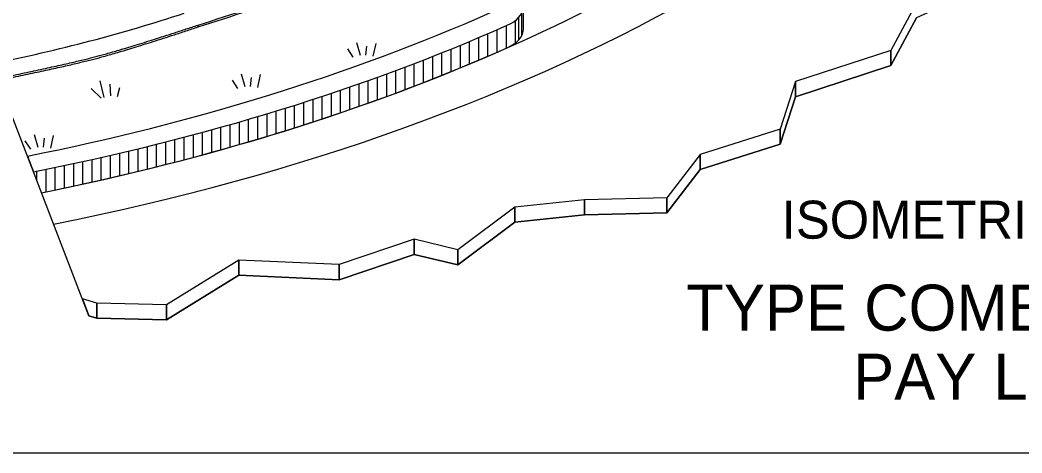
# Model space of a CAD drawing. Extents: x 103862 to 107151, y 100000 to 102076.
# Drawn here: x 105680.3 to 106115.6, y 99999.5 to 100187.5 of the extents above; entities that cross this region are included whole.
import ezdxf

# ---------------------------------------------------------------- set-up
doc = ezdxf.new("R2010")
doc.units = 0
for name, color, linetype in [('Level 1', 7, 'Continuous'), ('Level 10', 7, 'Continuous'), ('Level 11', 7, 'Continuous'), ('Level 18', 7, 'Continuous'), ('Level 19', 7, 'Continuous'), ('Level 2', 7, 'Continuous'), ('Level 20', 7, 'Continuous'), ('Level 3', 7, 'Continuous'), ('Level 4', 7, 'Continuous'), ('Level 45', 7, 'Continuous'), ('Level 57', 7, 'Continuous')]:
    doc.layers.add(name, color=color, linetype=linetype)

msp = doc.modelspace()

# ---------------------------------------------------------------- linework, layer by layer
at = {"layer": 'Level 1'}
msp.add_lwpolyline([(103862, 99999.5), (107151, 99999.5), (107151, 102075.5), (103862, 102075.5)], close=True, dxfattribs=at)
msp.add_lwpolyline([(103862, 99999.5), (107151, 99999.5), (107151, 102075.5), (103862, 102075.5)], close=True, dxfattribs=at)
msp.add_lwpolyline([(103862, 99999.5), (107151, 99999.5), (107151, 102075.5), (103862, 102075.5)], close=True, dxfattribs=at)
at = {"layer": 'Level 10'}
msp.add_line((105757.65, 100184.51), (105757.65, 100185.33), dxfattribs=at)
at = {"layer": 'Level 11'}
msp.add_line((105710.23, 100059.06), (105641.33, 100237.57), dxfattribs=at)
msp.add_lwpolyline([(106115.72, 100230.53), (106112.39, 100207.89), (106069.84, 100188.51), (106058.66, 100167.81), (106017.22, 100154.24), (106010.53, 100133.55), (105975.81, 100122.57), (105961.27, 100103.81), (105925.56, 100102.93), (105895.31, 100099.71), (105870.54, 100081.21), (105851.49, 100085.75), (105819.01, 100074.76), (105775.31, 100076.72), (105743.96, 100057.33), (105713.71, 100057.99), (105710.23, 100059.06)], dxfattribs=at)
at = {"layer": 'Level 18'}
for p, q in [((105826.49, 100177.77), (105828.07, 100172.23)), ((105822.53, 100175), (105824.9, 100171.44)), ((105830.84, 100176.19), (105830.44, 100172.23)), ((105834.8, 100177.38), (105833.61, 100171.83)), ((105716.88, 100153.95), (105715.1, 100161.06)), ((105772.38, 100161.43), (105774.75, 100157.86)), ((105776.33, 100164.2), (105777.92, 100158.66)), ((105780.69, 100162.62), (105780.29, 100158.66)), ((105784.64, 100163.8), (105783.46, 100158.26)), ((105715.46, 100153.59), (105711.19, 100157.86)), ((105719.72, 100154.66), (105719.36, 100159.64)), ((105722.56, 100154.3), (105723.63, 100158.21)), ((105682.42, 100135.02), (105684.79, 100131.45)), ((105686.37, 100137.79), (105687.96, 100132.25)), ((105690.73, 100136.21), (105690.33, 100132.25)), ((105694.68, 100137.39), (105693.5, 100131.85))]:
    msp.add_line(p, q, dxfattribs=at)
at = {"layer": 'Level 19'}
for p, q in [((105898.32, 100180.79), (105898.32, 100190.6)), ((105895.59, 100177.62), (105895.59, 100187.43)), ((105897.04, 100178.95), (105897.04, 100188.76)), ((105887.59, 100173.56), (105887.59, 100183.36)), ((105891.59, 100175.3), (105891.59, 100185.1)), ((105875.59, 100168.45), (105875.59, 100178.25)), ((105879.59, 100170.1), (105879.59, 100179.9)), ((105883.59, 100171.83), (105883.59, 100181.63)), ((105863.59, 100163.54), (105863.59, 100173.34)), ((105867.59, 100165.14), (105867.59, 100174.93)), ((105871.59, 100166.79), (105871.59, 100176.59)), ((105855.59, 100160.38), (105855.59, 100170.17)), ((105859.59, 100161.96), (105859.59, 100171.76)), ((105843.59, 100155.82), (105843.59, 100165.62)), ((105847.59, 100157.34), (105847.59, 100167.13)), ((105851.59, 100158.85), (105851.59, 100168.65)), ((105831.59, 100151.46), (105831.59, 100161.26)), ((105835.59, 100152.91), (105835.59, 100162.7)), ((105839.59, 100154.35), (105839.59, 100164.15)), ((105815.59, 100145.92), (105815.59, 100155.72)), ((105819.59, 100147.29), (105819.59, 100157.09)), ((105823.59, 100148.67), (105823.59, 100158.47)), ((105827.59, 100150.04), (105827.59, 100159.84)), ((105803.59, 100141.98), (105803.59, 100151.78)), ((105807.59, 100143.3), (105807.59, 100153.09)), ((105811.59, 100144.61), (105811.59, 100154.41)), ((105791.59, 100138.23), (105791.59, 100148.02)), ((105795.59, 100139.48), (105795.59, 100149.27)), ((105799.59, 100140.72), (105799.59, 100150.52)), ((105775.59, 100133.46), (105775.59, 100143.26)), ((105779.59, 100134.64), (105779.59, 100144.43)), ((105783.59, 100135.82), (105783.59, 100145.62)), ((105787.59, 100137.01), (105787.59, 100146.81)), ((105759.59, 100129), (105759.59, 100138.8)), ((105763.59, 100130.08), (105763.59, 100139.88)), ((105767.59, 100131.21), (105767.59, 100141)), ((105771.59, 100132.33), (105771.59, 100142.13)), ((105743.59, 100124.81), (105743.59, 100134.61)), ((105747.59, 100125.81), (105747.59, 100135.61)), ((105751.59, 100126.87), (105751.59, 100136.66)), ((105755.59, 100127.93), (105755.59, 100137.73)), ((105723.59, 100119.93), (105723.59, 100129.73)), ((105727.59, 100120.88), (105727.59, 100130.68)), ((105731.59, 100121.83), (105731.59, 100131.63)), ((105735.59, 100122.79), (105735.59, 100132.59)), ((105739.59, 100123.8), (105739.59, 100133.6)), ((105703.59, 100115.46), (105703.59, 100125.26)), ((105707.59, 100116.32), (105707.59, 100126.11)), ((105711.59, 100117.21), (105711.59, 100127.01)), ((105715.59, 100118.1), (105715.59, 100127.9)), ((105719.59, 100118.99), (105719.59, 100128.8)), ((105687.59, 100117.7), (105687.59, 100121.97)), ((105691.59, 100112.96), (105691.59, 100122.76)), ((105695.59, 100113.79), (105695.59, 100123.58)), ((105699.59, 100114.62), (105699.59, 100124.42))]:
    msp.add_line(p, q, dxfattribs=at)
at = {"layer": 'Level 2'}
msp.add_line((105899.05, 100183.72), (105899.05, 100193.52), dxfattribs=at)
msp.add_lwpolyline([(105683.44, 100128.45), (105686.07, 100121.65)], dxfattribs=at)
for centre, major_axis, ratio, start_param, end_param in [((105306.07, 100601.97), (893.91, 0), 0.54007, 5.241973, 5.356974), ((105306.07, 100601.15), (893.91, 0), 0.54007, 5.241973, 5.356974), ((105881.05, 100193.52), (18, 0), 0.57735, 5.36666, 7.068584), ((105500.85, 100431.43), (496.32, 0), 0.562493, 5.055802, 5.241972), ((105453.82, 100515.12), (708, 0), 0.57735, 5.042683, 5.36666), ((105453.82, 100515.12), (720, 0), 0.57735, 5.040825, 5.36666), ((105453.82, 100505.32), (720, 0), 0.57735, 5.045984, 5.36666)]:
    msp.add_ellipse(centre, major_axis=major_axis, ratio=ratio, start_param=start_param, end_param=end_param, dxfattribs=at)
for points in [[(105670.47, 100162.16), (105699.91, 100168.14), (105727.47, 100175.4), (105757.65, 100185.33)], [(105670.69, 100161.35), (105699.26, 100167.14), (105727.18, 100174.49), (105757.65, 100184.51)]]:
    msp.add_open_spline(points, degree=2, dxfattribs=at)
at = {"layer": 'Level 3'}
msp.add_lwpolyline([(105757.65, 100185.33), (105757.65, 100185.33)], dxfattribs=at)
at = {"layer": 'Level 4'}
for centre, major_axis, start_param, end_param in [((105453.82, 100505.32), (720, 0), 5.045984, 5.632303), ((105453.82, 100505.32), (744, 0), 5.04228, 5.497787), ((105881.05, 100183.72), (18, 0), 5.36666, 6.283699)]:
    msp.add_ellipse(centre, major_axis=major_axis, ratio=0.57735, start_param=start_param, end_param=end_param, dxfattribs=at)
at = {"layer": 'Level 45'}
for p, q in [((106069.84, 100195.04), (106058.66, 100174.34)), ((106058.66, 100167.81), (106069.84, 100188.51)), ((106058.66, 100174.34), (106017.22, 100160.78)), ((106058.66, 100174.34), (106058.66, 100167.81)), ((106058.66, 100167.81), (106058.66, 100174.34)), ((106017.22, 100154.24), (106058.66, 100167.81)), ((106017.22, 100160.78), (106010.53, 100140.08)), ((106017.22, 100160.78), (106017.22, 100154.24)), ((106017.22, 100154.24), (106017.22, 100160.78)), ((106010.53, 100133.55), (106017.22, 100154.24)), ((106010.53, 100140.08), (105975.81, 100129.1)), ((106010.53, 100140.08), (106010.53, 100133.55)), ((106010.53, 100133.55), (106010.53, 100140.08)), ((105975.81, 100122.57), (106010.53, 100133.55)), ((105975.81, 100129.1), (105961.27, 100110.34)), ((105975.81, 100129.1), (105975.81, 100122.57)), ((105975.81, 100122.57), (105975.81, 100129.1)), ((105961.27, 100103.81), (105975.81, 100122.57)), ((105925.56, 100109.46), (105895.31, 100106.24)), ((105961.27, 100110.34), (105925.56, 100109.46)), ((105925.56, 100109.46), (105925.56, 100102.93)), ((105925.56, 100102.93), (105925.56, 100109.46)), ((105961.27, 100110.34), (105961.27, 100103.81)), ((105961.27, 100103.81), (105961.27, 100110.34)), ((105895.31, 100106.24), (105870.54, 100087.74)), ((105895.31, 100106.24), (105895.31, 100099.71)), ((105895.31, 100099.71), (105895.31, 100106.24)), ((105925.56, 100102.93), (105961.27, 100103.81)), ((105870.54, 100081.21), (105895.31, 100099.71)), ((105895.31, 100099.71), (105925.56, 100102.93)), ((105851.49, 100092.28), (105819.01, 100081.3)), ((105870.54, 100087.74), (105851.49, 100092.28)), ((105851.49, 100092.28), (105851.49, 100085.75)), ((105851.49, 100085.75), (105851.49, 100092.28)), ((105870.54, 100087.74), (105870.54, 100081.21)), ((105870.54, 100081.21), (105870.54, 100087.74)), ((105775.31, 100083.26), (105743.96, 100063.86)), ((105775.31, 100076.72), (105775.31, 100083.26)), ((105819.01, 100081.3), (105775.31, 100083.26)), ((105775.31, 100083.26), (105775.31, 100076.72)), ((105819.01, 100074.76), (105851.49, 100085.75)), ((105851.49, 100085.75), (105870.54, 100081.21)), ((105819.01, 100081.3), (105819.01, 100074.76)), ((105819.01, 100074.76), (105819.01, 100081.3)), ((105743.96, 100057.33), (105775.31, 100076.72)), ((105775.31, 100076.72), (105819.01, 100074.76)), ((105713.71, 100064.52), (105707.37, 100066.46)), ((105743.96, 100063.86), (105713.71, 100064.52)), ((105713.71, 100064.52), (105713.71, 100057.99)), ((105713.71, 100057.99), (105713.71, 100064.52)), ((105743.96, 100063.86), (105743.96, 100057.33)), ((105743.96, 100057.33), (105743.96, 100063.86)), ((105710.23, 100059.06), (105713.71, 100057.99)), ((105713.71, 100057.99), (105743.96, 100057.33))]:
    msp.add_line(p, q, dxfattribs=at)
msp.add_lwpolyline([(105707.37, 100066.46), (105710.23, 100059.06)], dxfattribs=at)
at = {"layer": 'Level 57'}
for p, q in [((106069.84, 100195.04), (106058.66, 100174.34)), ((106069.84, 100188.51), (106058.66, 100167.81)), ((106058.66, 100174.34), (106017.22, 100160.78)), ((106058.66, 100167.81), (106058.66, 100174.34)), ((106058.66, 100167.81), (106017.22, 100154.24)), ((106017.22, 100160.78), (106010.53, 100140.08)), ((106017.22, 100154.24), (106017.22, 100160.78)), ((106017.22, 100154.24), (106010.53, 100133.55)), ((106010.53, 100140.08), (105975.81, 100129.1)), ((106010.53, 100133.55), (106010.53, 100140.08)), ((106010.53, 100133.55), (105975.81, 100122.57)), ((105975.81, 100129.1), (105961.27, 100110.34)), ((105975.81, 100122.57), (105975.81, 100129.1)), ((105975.81, 100122.57), (105961.27, 100103.81)), ((105925.56, 100109.46), (105895.31, 100106.24)), ((105961.27, 100110.34), (105925.56, 100109.46)), ((105925.56, 100102.93), (105925.56, 100109.46)), ((105961.27, 100103.81), (105961.27, 100110.34)), ((105895.31, 100106.24), (105870.54, 100087.74)), ((105895.31, 100099.71), (105895.31, 100106.24)), ((105961.27, 100103.81), (105925.56, 100102.93)), ((105895.31, 100099.71), (105870.54, 100081.21)), ((105925.56, 100102.93), (105895.31, 100099.71)), ((105851.49, 100092.28), (105819.01, 100081.3)), ((105870.54, 100087.74), (105851.49, 100092.28)), ((105851.49, 100085.75), (105851.49, 100092.28)), ((105870.54, 100081.21), (105870.54, 100087.74)), ((105775.31, 100083.26), (105743.96, 100063.86)), ((105775.31, 100076.72), (105775.31, 100083.26)), ((105819.01, 100081.3), (105775.31, 100083.26)), ((105851.49, 100085.75), (105819.01, 100074.76)), ((105870.54, 100081.21), (105851.49, 100085.75)), ((105819.01, 100074.76), (105819.01, 100081.3)), ((105775.31, 100076.72), (105743.96, 100057.33)), ((105819.01, 100074.76), (105775.31, 100076.72)), ((105713.71, 100064.52), (105707.37, 100066.46)), ((105713.71, 100057.99), (105713.71, 100064.52)), ((105743.96, 100063.86), (105713.71, 100064.52)), ((105743.96, 100057.33), (105743.96, 100063.86)), ((105713.71, 100057.99), (105710.23, 100059.06)), ((105743.96, 100057.33), (105713.71, 100057.99))]:
    msp.add_line(p, q, dxfattribs=at)

# ---------------------------------------------------------------- texts
at = {"layer": 'Level 20'}
for s, height, p in [('ISOMETRIC VIEW', 16.5, (106011.25, 100092.57)), ('TYPE COMBINATION', 20, (105969.77, 100052.61)), (' PAY LIMIT', 20, (106034.86, 100022.61))]:
    msp.add_text(s, height=height, dxfattribs=at).set_placement(p)

doc.saveas('drawing.dxf')
